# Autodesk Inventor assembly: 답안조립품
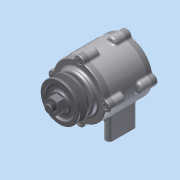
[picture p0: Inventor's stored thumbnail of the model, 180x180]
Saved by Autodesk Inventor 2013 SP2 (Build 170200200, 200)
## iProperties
Created: 2015-03
Part Number: 답안조립품
Document SubType Name: Assembly
Designer: dgall
Author: dgall
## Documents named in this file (11)
- C:\Documents and Settings\dgall\바탕 화면\450305V1040\답안조립품.iam
- C:\Documents and Settings\dgall\바탕 화면\450305V1040\본체.ipt
- C:\Documents and Settings\dgall\바탕 화면\450305V1040\축.ipt
- C:\Documents and Settings\dgall\바탕 화면\450305V1040\키(4 x 4 x 12).ipt
- C:\Documents and Settings\dgall\바탕 화면\450305V1040\V벨트풀리.ipt
- C:\Documents and Settings\dgall\바탕 화면\450305V1040\베어링 6204.ipt
- C:\Documents and Settings\dgall\바탕 화면\450305V1040\너트 M12x1.25.ipt
- C:\Documents and Settings\dgall\바탕 화면\450305V1040\커버.ipt
- C:\Documents and Settings\dgall\바탕 화면\450305V1040\커버2.ipt
- C:\Documents and Settings\dgall\바탕 화면\450305V1040\오일실.ipt
- C:\Documents and Settings\dgall\바탕 화면\450305V1040\M 4 x 12.ipt
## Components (14 placed, 6 different names)
1. KS B 1311 (I) 4 x 4 x 12:1
2. 그루브 풀리1:1
3. KS B 2023 6204 - 20 x 47 x 14:1
4. KS B 2023 6204 - 20 x 47 x 14:2
5. KS B 1012 클래스 1 일반 - 미터 M12x1.25:1
6. KS B 2804 D D - 20 32 8:1
7. KS B 1003 - 미터 M 4 x 12:2
8. KS B 1003 - 미터 M 4 x 12:3
9. KS B 1003 - 미터 M 4 x 12:4
10. KS B 1003 - 미터 M 4 x 12:5
11. KS B 1003 - 미터 M 4 x 12:1
12. KS B 1003 - 미터 M 4 x 12:6
13. KS B 1003 - 미터 M 4 x 12:7
14. KS B 1003 - 미터 M 4 x 12:8
